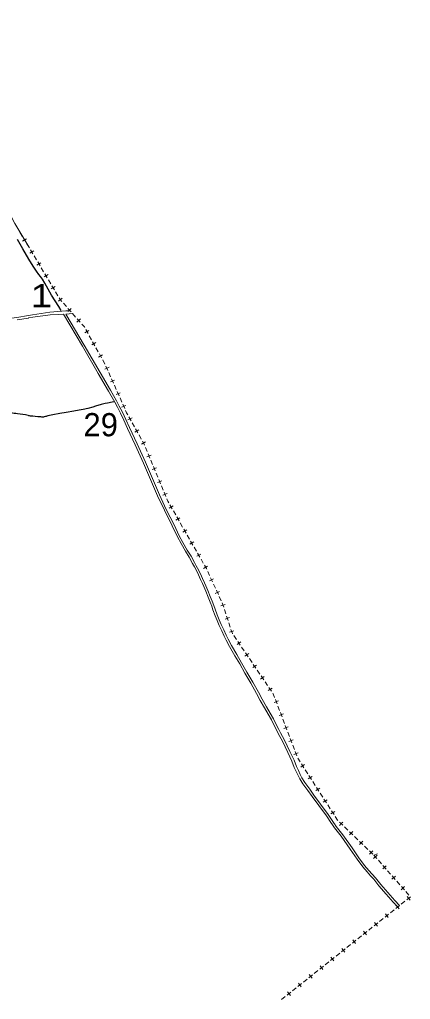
# Model space of a CAD drawing. Extents: x 476989 to 498418, y 4381813 to 4416555.
# Drawn here: x 487660 to 488503, y 4383749 to 4385862 of the extents above; entities that cross this region are included whole.
import ezdxf

# ---------------------------------------------------------------- set-up
doc = ezdxf.new("R2010")
doc.units = 0
doc.header["$LTSCALE"] = 20
for name, color, linetype, lineweight in [('13', 7, 'Continuous', 13), ('34', 7, 'Continuous', 13), ('36', 7, 'Continuous', 13), ('6', 7, 'Continuous', 25)]:
    doc.layers.add(name, color=color, linetype=linetype, lineweight=lineweight)

msp = doc.modelspace()

# ---------------------------------------------------------------- linework, layer by layer
at = {"layer": '34'}
for p, q in [((487660.88, 4385403.79), (487666.01, 4385395.21)), ((487675.43, 4385389.2), (487666.84, 4385384.07)), ((487668.57, 4385390.93), (487673.7, 4385382.34)), ((487676.26, 4385378.05), (487680.1, 4385371.63)), ((487680.1, 4385371.63), (487681.39, 4385369.47)), ((487690.81, 4385363.45), (487682.22, 4385358.33)), ((487683.95, 4385365.18), (487689.08, 4385356.6)), ((487691.65, 4385352.31), (487696.78, 4385343.72)), ((487706.19, 4385337.71), (487697.61, 4385332.58)), ((487699.34, 4385339.44), (487704.47, 4385330.85)), ((487707.03, 4385326.56), (487712.16, 4385317.98)), ((487721.58, 4385311.97), (487712.99, 4385306.84)), ((487714.72, 4385313.69), (487719.85, 4385305.11)), ((487722.41, 4385300.82), (487727.54, 4385292.23)), ((487730.1, 4385287.95), (487735.23, 4385279.37)), ((487736.96, 4385286.22), (487728.38, 4385281.09)), ((487737.8, 4385275.07), (487742.93, 4385266.49)), ((487751.82, 4385261.23), (487744.31, 4385254.62)), ((487754.68, 4385250.42), (487761.29, 4385242.92)), ((487771.65, 4385238.73), (487764.14, 4385232.12)), ((487764.59, 4385239.18), (487771.2, 4385231.68)), ((487774.51, 4385227.92), (487781.12, 4385220.42)), ((487791.48, 4385216.23), (487783.97, 4385209.62)), ((487784.42, 4385216.68), (487791.03, 4385209.18)), ((487809.92, 4385191.44), (487801.18, 4385186.58)), ((487803.12, 4385193.38), (487807.98, 4385184.64)), ((487810.4, 4385180.27), (487815.26, 4385171.53)), ((487824.48, 4385165.23), (487815.74, 4385160.37)), ((487817.68, 4385167.17), (487822.54, 4385158.43)), ((487824.97, 4385154.06), (487829.83, 4385145.31)), ((487832.25, 4385140.95), (487837.11, 4385132.21)), ((487839.05, 4385139.01), (487830.31, 4385134.15)), ((487839.53, 4385127.84), (487844.39, 4385119.1)), ((487853.11, 4385112.03), (487843.96, 4385107.99)), ((487846.51, 4385114.59), (487850.56, 4385105.44)), ((487852.58, 4385100.87), (487856.62, 4385091.72)), ((487865.24, 4385084.61), (487856.09, 4385080.56)), ((487858.64, 4385087.16), (487862.69, 4385078.01)), ((487864.71, 4385073.44), (487868.75, 4385064.29)), ((487877.37, 4385057.18), (487868.22, 4385053.14)), ((487870.77, 4385059.73), (487874.82, 4385050.59)), ((487876.84, 4385046.01), (487880.89, 4385036.87)), ((487889.5, 4385029.75), (487880.35, 4385025.71)), ((487882.9, 4385032.3), (487886.95, 4385023.16)), ((487902.68, 4385003.38), (487893.96, 4384998.49)), ((487895.88, 4385005.3), (487900.77, 4384996.58)), ((487903.21, 4384992.21), (487908.1, 4384983.49)), ((487917.35, 4384977.22), (487908.63, 4384972.33)), ((487910.54, 4384979.14), (487915.43, 4384970.42)), ((487917.88, 4384966.06), (487922.77, 4384957.33)), ((487932.01, 4384951.06), (487923.29, 4384946.17)), ((487931.57, 4384939.42), (487935.41, 4384930.19)), ((487943.86, 4384922.89), (487934.63, 4384919.04)), ((487937.33, 4384925.58), (487941.17, 4384916.35)), ((487943.09, 4384911.73), (487946.93, 4384902.5)), ((487955.38, 4384895.2), (487946.15, 4384891.35)), ((487948.85, 4384897.89), (487952.69, 4384888.66)), ((487954.61, 4384884.04), (487958.45, 4384874.81)), ((487966.9, 4384867.51), (487957.67, 4384863.66)), ((487960.36, 4384870.2), (487964.2, 4384860.97)), ((487966.13, 4384856.35), (487969.97, 4384847.12)), ((487978.42, 4384839.82), (487969.19, 4384835.98)), ((487971.88, 4384842.51), (487975.72, 4384833.28)), ((487991.22, 4384813.46), (487982.54, 4384808.49)), ((487984.4, 4384815.31), (487989.37, 4384806.63)), ((487991.85, 4384802.3), (487996.82, 4384793.62)), ((488006.12, 4384787.43), (487997.44, 4384782.46)), ((487999.3, 4384789.29), (488004.27, 4384780.61)), ((488006.75, 4384776.27), (488011.72, 4384767.59)), ((488021.02, 4384761.4), (488012.34, 4384756.44)), ((488014.2, 4384763.26), (488019.16, 4384754.58)), ((488021.65, 4384750.24), (488026.62, 4384741.56)), ((488035.92, 4384735.38), (488027.24, 4384730.41)), ((488029.1, 4384737.23), (488034.06, 4384728.55)), ((488036.55, 4384724.21), (488041.52, 4384715.53)), ((488050.82, 4384709.35), (488042.14, 4384704.38)), ((488043.99, 4384711.2), (488048.96, 4384702.52)), ((488051.45, 4384698.19), (488056.41, 4384689.51)), ((488065.72, 4384683.32), (488057.04, 4384678.35)), ((488065.82, 4384671.89), (488070, 4384662.8)), ((488078.72, 4384655.82), (488069.64, 4384651.64)), ((488072.09, 4384658.27), (488076.27, 4384649.19)), ((488078.36, 4384644.65), (488082.54, 4384635.56)), ((488091.26, 4384628.58), (488082.18, 4384624.4)), ((488084.63, 4384631.03), (488088.81, 4384621.95)), ((488090.91, 4384617.4), (488095.09, 4384608.32)), ((488103.7, 4384600.68), (488094.19, 4384597.56)), ((488102.06, 4384589.62), (488105.18, 4384580.12)), ((488113.05, 4384572.18), (488103.54, 4384569.07)), ((488106.74, 4384575.38), (488109.85, 4384565.88)), ((488111.41, 4384561.12), (488114.53, 4384551.62)), ((488122.4, 4384543.69), (488112.89, 4384540.57)), ((488122.17, 4384533.32), (488127.77, 4384525.04)), ((488137.51, 4384519.57), (488129.23, 4384513.96)), ((488130.57, 4384520.91), (488136.18, 4384512.62)), ((488138.98, 4384508.48), (488144.59, 4384500.2)), ((488154.33, 4384494.73), (488146.05, 4384489.13)), ((488147.38, 4384496.07), (488152.99, 4384487.79)), ((488155.79, 4384483.65), (488161.4, 4384475.37)), ((488171.14, 4384469.9), (488162.86, 4384464.29)), ((488164.19, 4384471.24), (488169.8, 4384462.95)), ((488172.6, 4384458.81), (488178.21, 4384450.53)), ((488187.95, 4384445.06), (488179.67, 4384439.46)), ((488181.01, 4384446.4), (488186.61, 4384438.12)), ((488189.41, 4384433.98), (488195.02, 4384425.7)), ((488197.82, 4384421.57), (488203.42, 4384413.28)), ((488204.76, 4384420.23), (488196.48, 4384414.62)), ((488218.3, 4384392.39), (488208.96, 4384388.83)), ((488211.85, 4384395.28), (488215.41, 4384385.94)), ((488217.19, 4384381.27), (488220.76, 4384371.92)), ((488228.99, 4384364.37), (488219.64, 4384360.81)), ((488222.53, 4384367.26), (488226.1, 4384357.92)), ((488227.88, 4384353.25), (488231.44, 4384343.9)), ((488239.67, 4384336.35), (488230.33, 4384332.79)), ((488233.22, 4384339.24), (488236.78, 4384329.9)), ((488238.56, 4384325.22), (488242.12, 4384315.88)), ((488250.36, 4384308.33), (488241.01, 4384304.76)), ((488243.9, 4384311.22), (488247.47, 4384301.87)), ((488249.25, 4384297.2), (488252.81, 4384287.86)), ((488261.04, 4384280.31), (488251.7, 4384276.74)), ((488254.59, 4384283.2), (488258.15, 4384273.85)), ((488274.9, 4384255.04), (488266.48, 4384249.64)), ((488267.99, 4384256.55), (488273.39, 4384248.13)), ((488276.09, 4384243.92), (488281.5, 4384235.51)), ((488284.19, 4384231.31), (488289.59, 4384222.89)), ((488291.1, 4384229.8), (488282.68, 4384224.4)), ((488292.29, 4384218.68), (488297.69, 4384210.27)), ((488307.3, 4384204.56), (488298.88, 4384199.16)), ((488300.39, 4384206.07), (488305.79, 4384197.65)), ((488308.49, 4384193.44), (488313.89, 4384185.03)), ((488323.5, 4384179.32), (488315.08, 4384173.92)), ((488316.59, 4384180.83), (488321.99, 4384172.41)), ((488324.69, 4384168.21), (488330.09, 4384159.79)), ((488339.69, 4384154.08), (488331.28, 4384148.68)), ((488332.79, 4384155.59), (488338.19, 4384147.17)), ((488349.98, 4384131.17), (488353.26, 4384128.02)), ((488353.89, 4384128.02), (488350.12, 4384124.1)), ((488353.26, 4384128.02), (488357.19, 4384124.24)), ((488357.05, 4384131.31), (488353.89, 4384128.02)), ((488360.79, 4384120.77), (488368, 4384113.84)), ((488371.6, 4384110.38), (488378.81, 4384103.45)), ((488378.67, 4384110.52), (488371.74, 4384103.32)), ((488382.41, 4384099.99), (488389.62, 4384093.06)), ((488393.22, 4384089.6), (488400.43, 4384082.67)), ((488400.29, 4384089.74), (488393.36, 4384082.53)), ((488404.03, 4384079.2), (488411.24, 4384072.27)), ((488414.84, 4384068.81), (488422.04, 4384061.88)), ((488421.9, 4384068.95), (488414.97, 4384061.74)), ((488432.07, 4384062.39), (488424, 4384060)), ((488431.05, 4384059.55), (488423.53, 4384052.95)), ((488424, 4384060), (488430.59, 4384052.49)), ((488433.89, 4384048.73), (488440.49, 4384041.22)), ((488450.83, 4384037.01), (488443.32, 4384030.41)), ((488443.78, 4384037.47), (488450.37, 4384029.95)), ((488453.67, 4384026.2), (488460.27, 4384018.68)), ((488470.62, 4384014.47), (488463.1, 4384007.87)), ((488463.56, 4384014.93), (488470.16, 4384007.41)), ((488473.46, 4384003.66), (488480.05, 4383996.14)), ((488490.4, 4383991.93), (488482.89, 4383985.34)), ((488483.35, 4383992.39), (488489.94, 4383984.88)), ((488493.24, 4383981.12), (488499.84, 4383973.6)), ((488491.12, 4383960.53), (488483.3, 4383954.3)), ((488502.85, 4383969.88), (488495.03, 4383963.65)), ((488502.05, 4383962.85), (488495.82, 4383970.67)), ((488467.66, 4383941.84), (488459.84, 4383935.61)), ((488479.39, 4383951.19), (488471.57, 4383944.95)), ((488478.6, 4383944.16), (488472.37, 4383951.98)), ((488432.49, 4383913.8), (488424.67, 4383907.57)), ((488431.69, 4383906.78), (488425.46, 4383914.6)), ((488444.21, 4383923.15), (488436.39, 4383916.91)), ((488455.94, 4383932.5), (488448.12, 4383926.26)), ((488455.15, 4383925.47), (488448.91, 4383933.29)), ((488409.04, 4383895.11), (488401.22, 4383888.88)), ((488408.24, 4383888.09), (488402.01, 4383895.91)), ((488420.76, 4383904.46), (488412.94, 4383898.22)), ((488385.58, 4383876.42), (488377.76, 4383870.19)), ((488384.79, 4383869.39), (488378.56, 4383877.21)), ((488397.31, 4383885.76), (488389.48, 4383879.53)), ((488362.13, 4383857.73), (488354.31, 4383851.5)), ((488361.34, 4383850.7), (488355.1, 4383858.52)), ((488373.85, 4383867.07), (488366.03, 4383860.84)), ((488326.95, 4383829.69), (488319.13, 4383823.46)), ((488338.68, 4383839.04), (488330.86, 4383832.81)), ((488337.88, 4383832.01), (488331.65, 4383839.83)), ((488350.4, 4383848.38), (488342.58, 4383842.15)), ((488303.49, 4383811), (488295.67, 4383804.77)), ((488315.22, 4383820.35), (488307.4, 4383814.11)), ((488314.43, 4383813.32), (488308.2, 4383821.14)), ((488280.04, 4383792.31), (488272.22, 4383786.07)), ((488291.77, 4383801.66), (488283.95, 4383795.42)), ((488290.98, 4383794.63), (488284.75, 4383802.45)), ((488256.59, 4383773.62), (488248.77, 4383767.38)), ((488268.32, 4383782.96), (488260.5, 4383776.73)), ((488267.52, 4383775.94), (488261.29, 4383783.76)), ((488233.14, 4383754.92), (488225.32, 4383748.69)), ((488244.87, 4383764.27), (488237.05, 4383758.04)), ((488244.07, 4383757.25), (488237.84, 4383765.07))]:
    msp.add_line(p, q, dxfattribs=at)
for points in [[(487280.6, 4386441.97), (487080, 4386339), (487267, 4386051), (487354, 4385933), (487441, 4385795), (487598, 4385523), (487650, 4385422), (487680.1, 4385371.64)], [(487745.49, 4385262.21), (487748, 4385258), (487751.37, 4385254.17)], [(487794.34, 4385205.43), (487800, 4385199), (487800.7, 4385197.75)], [(487888.97, 4385018.59), (487891, 4385014), (487893.44, 4385009.65)], [(487925.21, 4384952.98), (487928, 4384948), (487929.65, 4384944.04)], [(487977.64, 4384828.66), (487980, 4384823), (487981.92, 4384819.64)], [(488058.89, 4384685.18), (488063, 4384678), (488063.72, 4384676.43)], [(488097.18, 4384603.79), (488098, 4384602), (488100.5, 4384594.37)], [(488116.09, 4384546.88), (488119, 4384538), (488119.37, 4384537.46)], [(488206.23, 4384409.14), (488207, 4384408), (488210.07, 4384399.95)], [(488259.93, 4384269.18), (488260, 4384269), (488265.3, 4384260.75)], [(488340.89, 4384142.97), (488346, 4384135), (488346.38, 4384134.63)]]:
    msp.add_lwpolyline(points, dxfattribs=at)
at = {"layer": '36'}
for p, q in [((487679.81, 4385224.07), (487679.85, 4385224.08)), ((487760.04, 4385226.64), (487774.07, 4385228.14)), ((487679.8, 4385218.38), (487679.84, 4385218.39)), ((488332.78, 4384128.05), (488333.4, 4384127.12)), ((488338.74, 4384128.04), (488339.36, 4384127.11))]:
    msp.add_line(p, q, dxfattribs=at)
for points in [[(487497.15, 4385199.42), (487509.69, 4385199.56), (487530.73, 4385201.64), (487543.2, 4385202.51), (487556.97, 4385203.85), (487571.79, 4385206.52), (487597.97, 4385211.35), (487621.23, 4385214.93), (487654.34, 4385219.7), (487679.81, 4385224.07)], [(487679.84, 4385218.39), (487689.06, 4385219.97), (487725.96, 4385225.31), (487743.45, 4385226.24), (487754.77, 4385226.5)], [(487679.85, 4385224.08), (487688.19, 4385225.51), (487725.41, 4385230.89), (487751.05, 4385232.88)], [(487751.51, 4385233.11), (487760.04, 4385233.57), (487770.05, 4385233.8)], [(487754.77, 4385226.5), (487795.93, 4385157.57), (487829.92, 4385098.83), (487852.21, 4385060.31)], [(487760.04, 4385226.64), (487799.89, 4385159.9), (487833.9, 4385101.14), (487856.19, 4385062.62)], [(487655.21, 4385214.16), (487679.8, 4385218.38)], [(487852.21, 4385060.31), (487865.52, 4385037.09), (487871.17, 4385026.06), (487877.83, 4385013.17), (487885.41, 4384997.67), (487892.78, 4384980.04), (487909.58, 4384945.08), (487927.48, 4384905.25), (487957.67, 4384834.81), (487972.51, 4384803.57), (487989.09, 4384770.37), (488000.47, 4384746.72), (488008.53, 4384731.68), (488017.92, 4384715.2), (488026.08, 4384702.24), (488033.4, 4384688.72), (488037.26, 4384681.81), (488039.95, 4384676.45), (488045.87, 4384664.41), (488050.54, 4384654.49), (488054.62, 4384645.57), (488057.39, 4384639.08), (488062.05, 4384628.97), (488066.76, 4384615.91), (488071.16, 4384605.55), (488074.65, 4384596.59), (488077, 4384588.77)], [(487856.19, 4385062.62), (487869.5, 4385039.41), (487875.26, 4385028.16), (487881.94, 4385015.24), (487889.6, 4384999.57), (487896.98, 4384981.93), (487913.76, 4384947.02), (487931.69, 4384907.09), (487961.86, 4384836.7), (487976.64, 4384805.58), (487993.22, 4384772.4), (488004.57, 4384748.81), (488012.55, 4384733.91), (488021.87, 4384717.57), (488030.06, 4384704.56), (488037.43, 4384690.93), (488041.33, 4384683.96), (488044.07, 4384678.49), (488050.02, 4384666.41), (488054.72, 4384656.43), (488058.83, 4384647.43), (488061.6, 4384640.95), (488066.31, 4384630.72), (488071.05, 4384617.59), (488075.42, 4384607.28), (488078.92, 4384598.31), (488081.65, 4384590.5)], [(488081.65, 4384590.5), (488086.37, 4384577.81), (488090.65, 4384567.62), (488095.25, 4384557.47), (488100.6, 4384545.98), (488105.56, 4384534.32), (488109.92, 4384525.64), (488117.24, 4384512.11), (488128.55, 4384492.58), (488139.09, 4384474.89), (488150.57, 4384454.8), (488162.92, 4384432.9), (488175.67, 4384411.04), (488183.45, 4384396.02), (488192.62, 4384379.97), (488200.42, 4384366.3), (488207.44, 4384354.1), (488214.28, 4384340.4), (488219.04, 4384330.9), (488222.99, 4384323.32), (488231.38, 4384308.11), (488243.29, 4384283.17), (488252.18, 4384264.54), (488257.14, 4384250.9), (488261.27, 4384242.16), (488265.21, 4384233.89), (488268.91, 4384226.73), (488275.32, 4384216.42), (488285.7, 4384202.17), (488294.93, 4384189.09), (488309.18, 4384169.66), (488325.75, 4384147.54), (488338.74, 4384128.04)], [(488077, 4384588.77), (488081.75, 4384575.98), (488086.1, 4384565.63), (488090.74, 4384555.4), (488096.06, 4384543.96), (488101.05, 4384532.24), (488105.52, 4384523.34), (488112.91, 4384509.68), (488124.28, 4384490.07), (488134.8, 4384472.39), (488146.25, 4384452.35), (488158.62, 4384430.43), (488171.32, 4384408.65), (488179.09, 4384393.64), (488188.32, 4384377.51), (488196.12, 4384363.84), (488203.07, 4384351.75), (488209.85, 4384338.18), (488214.63, 4384328.65), (488218.61, 4384320.97), (488226.97, 4384305.84), (488238.81, 4384281.03), (488247.6, 4384262.62), (488252.55, 4384248.99), (488256.79, 4384240.03), (488260.77, 4384231.68), (488264.59, 4384224.27), (488271.21, 4384213.65), (488281.67, 4384199.28), (488290.9, 4384186.19), (488305.19, 4384166.71), (488321.7, 4384144.67), (488332.78, 4384128.05)], [(488333.4, 4384127.12), (488338.92, 4384118.84), (488353.38, 4384100.94), (488373.15, 4384072.85), (488387.79, 4384050.88), (488400.24, 4384034.62), (488409.33, 4384023.73), (488416.52, 4384015.35), (488424.19, 4384007.74), (488435.14, 4383993.67), (488450.82, 4383975.8), (488465.89, 4383958.57), (488475.23, 4383948.42)], [(488339.36, 4384127.11), (488342.92, 4384121.78), (488357.34, 4384103.93), (488377.25, 4384075.65), (488391.83, 4384053.77), (488404.12, 4384037.72), (488413.11, 4384026.93), (488420.16, 4384018.74), (488427.91, 4384011.04), (488438.97, 4383996.84), (488454.55, 4383979.06), (488469.58, 4383961.88), (488479.08, 4383951.57)]]:
    msp.add_lwpolyline(points, dxfattribs=at)
at = {"layer": '6'}
for points in [[(487680, 4385345.5), (487666.97, 4385367.8), (487655.53, 4385387.66)], [(487750.13, 4385234.72), (487744.74, 4385242.95), (487729.34, 4385267.75), (487714.67, 4385293.38), (487709.58, 4385302.34), (487705.22, 4385308.13), (487701.54, 4385312.54), (487696.47, 4385319.22), (487690.86, 4385327.71), (487682.31, 4385341.56), (487680.05, 4385345.41)], [(487865.21, 4385037.63), (487859.62, 4385036.92), (487850.2, 4385034.95), (487845.15, 4385034.12), (487835.92, 4385031.69), (487824.31, 4385028.1), (487818.44, 4385026.24), (487807.39, 4385023.47), (487797.39, 4385021.15), (487788.46, 4385019.33), (487777.26, 4385017.69), (487760.7, 4385014.55), (487747, 4385012.27), (487732.17, 4385009.18), (487721.55, 4385007.15), (487719.36, 4385006.58), (487717.38, 4385006.15), (487716.36, 4385005.78), (487715.95, 4385005.62), (487713.55, 4385004.93)]]:
    msp.add_lwpolyline(points, dxfattribs=at)
for points in [[(487503.02, 4385116.48), (487517.08, 4385103.65), (487539.5, 4385086.52), (487549.79, 4385077.07), (487559.41, 4385067.47), (487578.99, 4385051.21), (487590.49, 4385042.04), (487603.03, 4385032.63), (487610.45, 4385026.75), (487614.38, 4385023.32), (487616.24, 4385022.01), (487617.43, 4385021.32), (487619.51, 4385019.87), (487621.29, 4385018.79), (487632.76, 4385015.64), (487641.4, 4385014.37), (487655.73, 4385012.48), (487679.12, 4385009.11)], [(487679.48, 4385008.17), (487682.96, 4385007.7), (487705.29, 4385005.58), (487713.54, 4385005.01)]]:
    msp.add_spline(points, degree=3, dxfattribs=at)

# ---------------------------------------------------------------- texts
at = {"layer": '13', "width": 1.25}
msp.add_text('1', height=50, dxfattribs=at).set_placement((487684.03, 4385241.38))
at = {"layer": '13'}
msp.add_text('29', height=50, dxfattribs=at).set_placement((487798.02, 4384963.25))

doc.saveas('drawing.dxf')
